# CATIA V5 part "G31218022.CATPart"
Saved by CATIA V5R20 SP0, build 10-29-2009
Part number: G31218022
Revision: 7
Definition: design
Nomenclature: G31218022
Source: made
Description: NOT SPECIFIED
Bounding box of the stored display mesh (mm): x -8 to 22, y -15.5 to 15.5, z -15.5 to 15.5
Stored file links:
  C:\Users\Raffaele\Desktop\3D X SITO CF\BOLEX\23-BUSH REF 312\G31218022.CATPart

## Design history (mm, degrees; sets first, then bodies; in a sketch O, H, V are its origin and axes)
Body1 "MANIFOLD_SOLID_BREP #5929" (main body)
  Solid1: solid without history
Body2 "MANIFOLD_SOLID_BREP #6072"
  Solid2: solid without history
Body3 "MANIFOLD_SOLID_BREP #6215"
  Solid3: solid without history
Body4 "MANIFOLD_SOLID_BREP #6358"
  Solid4: solid without history
Body5 "MANIFOLD_SOLID_BREP #6501"
  Solid5: solid without history
Body6 "MANIFOLD_SOLID_BREP #6646"
  Solid6: solid without history
Body7 "MANIFOLD_SOLID_BREP #6791"
  Solid7: solid without history
Body8 "MANIFOLD_SOLID_BREP #6936"
  Solid8: solid without history
Body9 "MANIFOLD_SOLID_BREP #7081"
  Solid9: solid without history
Body10 "MANIFOLD_SOLID_BREP #7226"
  Solid10: solid without history
Body11 "MANIFOLD_SOLID_BREP #7371"
  Solid11: solid without history
Body12 "MANIFOLD_SOLID_BREP #7516"
  Solid12: solid without history
Body13 "MANIFOLD_SOLID_BREP #7661"
  Solid13: solid without history
Body14 "MANIFOLD_SOLID_BREP #7806"
  Solid14: solid without history
Body15 "MANIFOLD_SOLID_BREP #7951"
  Solid15: solid without history
Body16 "MANIFOLD_SOLID_BREP #8096"
  Solid16: solid without history
Body17 "MANIFOLD_SOLID_BREP #8241"
  Solid17: solid without history
Body18 "MANIFOLD_SOLID_BREP #8386"
  Solid18: solid without history
Body19 "MANIFOLD_SOLID_BREP #8531"
  Solid19: solid without history
Body20 "MANIFOLD_SOLID_BREP #8678"
  Solid20: solid without history
Body21 "MANIFOLD_SOLID_BREP #8825"
  Solid21: solid without history
Body22 "MANIFOLD_SOLID_BREP #8970"
  Solid22: solid without history
Body23 "MANIFOLD_SOLID_BREP #9117"
  Solid23: solid without history
Body24 "MANIFOLD_SOLID_BREP #9264"
  Solid24: solid without history
Body25 "MANIFOLD_SOLID_BREP #9409"
  Solid25: solid without history
Body26 "MANIFOLD_SOLID_BREP #9554"
  Solid26: solid without history
Body27 "MANIFOLD_SOLID_BREP #9699"
  Solid27: solid without history
Body28 "MANIFOLD_SOLID_BREP #9844"
  Solid28: solid without history
Body29 "MANIFOLD_SOLID_BREP #9989"
  Solid29: solid without history
Body30 "MANIFOLD_SOLID_BREP #10134"
  Solid30: solid without history
Body31 "MANIFOLD_SOLID_BREP #10279"
  Solid31: solid without history
Body32 "MANIFOLD_SOLID_BREP #10422"
  Solid32: solid without history
Body33 "MANIFOLD_SOLID_BREP #10565"
  Solid33: solid without history
Body34 "MANIFOLD_SOLID_BREP #10710"
  Solid34: solid without history
Body35 "MANIFOLD_SOLID_BREP #10855"
  Solid35: solid without history
Body36 "MANIFOLD_SOLID_BREP #11002"
  Solid36: solid without history
Body37 "MANIFOLD_SOLID_BREP #11149"
  Solid37: solid without history
Body38 "MANIFOLD_SOLID_BREP #11294"
  Solid38: solid without history
Body39 "MANIFOLD_SOLID_BREP #11441"
  Solid39: solid without history
Body40 "MANIFOLD_SOLID_BREP #11588"
  Solid40: solid without history
Body41 "MANIFOLD_SOLID_BREP #11733"
  Solid41: solid without history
